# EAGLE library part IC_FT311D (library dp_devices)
USB Android Host Mfr no: FT311D-32L1C FT311D
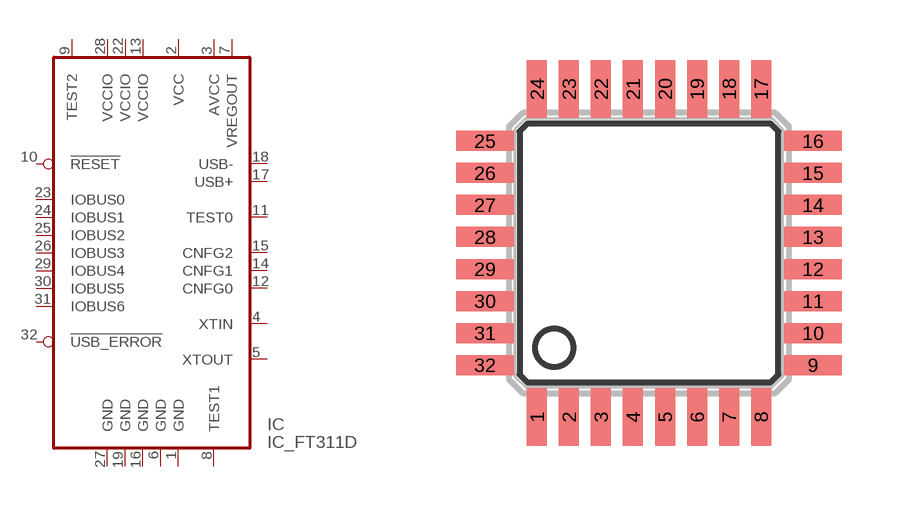
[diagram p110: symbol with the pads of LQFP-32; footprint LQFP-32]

Designator prefix IC

## IC_FT311D-LQFP-32  [LQFP-32]
1  GND  sup
2  VCC  sup
3  AVCC  pwr
4  XTIN  in
5  XTOUT  out
6  GND  sup
7  VREGOUT  pwr
8  TEST1  in
9  TEST2  in
10  !RESET  in
11  TEST0  out
12  CNFG0  in
13  VCCIO  sup
14  CNFG1  in
15  CNFG2  in
16  GND  sup
17  USB+  out
18  USB-  in
19  GND  sup
22  VCCIO  sup
23  IOBUS0
24  IOBUS1
25  IOBUS2
26  IOBUS3
27  GND  sup
28  VCCIO  sup
29  IOBUS4
30  IOBUS5
31  IOBUS6
32  !USB_ERROR  out

## Footprint LQFP-32 (pad centres in mm)
smd 0.5 x 1.45: 1 -2.8,-4.1; 2 -2,-4.1; 3 -1.2,-4.1; 4 -0.4,-4.1; 5 0.4,-4.1; 6 1.2,-4.1; 7 2,-4.1; 8 2.8,-4.1; 17 2.8,4.1; 18 2,4.1; 19 1.2,4.1; 20 0.4,4.1; 21 -0.4,4.1; 22 -1.2,4.1; 23 -2,4.1; 24 -2.8,4.1
smd 1.45 x 0.5: 9 4.1,-2.8; 10 4.1,-2; 11 4.1,-1.2; 12 4.1,-0.4; 13 4.1,0.4; 14 4.1,1.2; 15 4.1,2; 16 4.1,2.8; 25 -4.1,2.8; 26 -4.1,2; 27 -4.1,1.2; 28 -4.1,0.4; 29 -4.1,-0.4; 30 -4.1,-1.2; 31 -4.1,-2; 32 -4.1,-2.8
